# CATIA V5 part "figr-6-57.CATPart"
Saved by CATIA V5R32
Part number: Part1
Bounding box of the stored display mesh (mm): x -50.648 to 50.648, y -72.183 to 72.183, z -40 to 40
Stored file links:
  D:\PROJECTS\Project 2022\CATIA V5 6R 2022\Resources\Part Files\c06_catia_v5_6r2022_prt\figr-6-57.CATPart
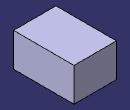
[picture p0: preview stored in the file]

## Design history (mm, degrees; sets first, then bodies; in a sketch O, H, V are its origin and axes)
Body1 (main body)
  Sketch1 on xy-plane, origin (0, 0, 0), H (1, 0, 0), V (0, 1, 0)
    line L1 (-50.6478, 72.1832) -> (50.6478, 72.1832)
    line L2 (50.6478, 72.1832) -> (50.6478, -72.1832)
    line L3 (50.6478, -72.1832) -> (-50.6478, -72.1832)
    line L4 (-50.6478, -72.1832) -> (-50.6478, 72.1832)
    axis line L5 (50.6478, -72.1832) -> (-50.6478, 72.1832)
    horizontal: L1 H, L3 H
    vertical: L2 V, L4 V
    midpoint: O L5
  Pad1: profile Sketch1, direction (0, 0, 1), length 40, mirrored extent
